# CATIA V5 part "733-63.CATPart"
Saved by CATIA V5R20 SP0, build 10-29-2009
Part number: 733-63
Bounding box of the stored display mesh (mm): x -47.5 to 47.5, y -47.5 to 47.5, z -60 to 90
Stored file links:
  C:\Users\Utente\Desktop\IO LAVORO\3D X SITO CF\X SITO\733\733-63.CATPart
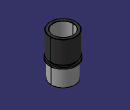
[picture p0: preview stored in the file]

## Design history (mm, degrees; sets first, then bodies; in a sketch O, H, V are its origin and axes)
Set1
  DatumSurface1 to DatumSurface25 "733-63"
Body1 (main body)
